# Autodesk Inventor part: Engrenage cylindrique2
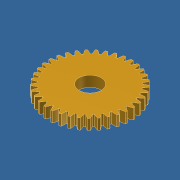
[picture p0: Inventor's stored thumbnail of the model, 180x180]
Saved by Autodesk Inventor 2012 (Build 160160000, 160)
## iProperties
Created: 2011-10
Part Number: Engrenage cylindrique2
Material: Laiton (jaune doux)
Document SubType Name: Modeling
Designer: Laur
Mass: 0.65097 g
Surface Area: 1.97897 cm^2
Volume: 0.076856 cm^3
Density: 8.47 g/cm^3
CustomPartVersion: 1
Author: Laur
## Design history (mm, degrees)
sketch "Sketch1"
  geometry: C1 r 4.78 at (0, 0)
  constraints: 1 centre point
  dimensions: "d0" = 9.56 diameter of C1 (= da_da)
extrude "Extrusion1" new body sketch "Sketch1" distance "d1" = 1.2 (= da_b); taper "d2" = 0 deg
workplane "Work Plane2"
sketch "Sketch2"
  geometry: C1 r 4.78 at (0, 0) reference; C2 r 4.625 at (0, 0)
  constraints: 1 centre point, 1 coincident
  dimensions: "d3" = 9.25 diameter of C2 (= da_dw)
extrude_surface "ExtrusionSrf1" sketch "Sketch2" dims "d4" = 10, "d5" = 0
workplane "Work Plane8"
workplane "Work Plane9"
feature "Engrenage cylindrique" dims "da_b" = 1.2, "da_d" = 9.25, "da_aw" = 6, "da_da" = 9.56, "da_df" = 8.435, "da_dw" = 9.25, angle "da_beta" = 0 deg, "da_lefttooth" = 0, "da_righttooth" = 0
sketch "Esquisse3"
  geometry: C1 r 1.25 at (0, 0) reference
extrude "alésage" cut sketch "Esquisse3" stored distance "d49" = 10; taper "d50" = 0 deg
node "Solide1"
node "Corps solides"
node "Corps surfaciques"
body "Srf1"
node "Référence2"
other parameters: "d16" = 6 (= da_aw), "d17" = 0, "d34" = 0.84908 (computed from da_z), "d39" = 0, "d41" = 0, "d43" = 6 (= da_aw), "d46" = 6 (= da_aw), "d47" = 0, "d48" = 0
